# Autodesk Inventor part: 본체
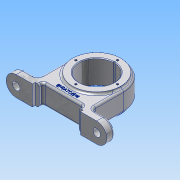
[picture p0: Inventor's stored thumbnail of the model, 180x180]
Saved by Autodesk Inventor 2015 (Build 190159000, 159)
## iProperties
Created: 2019-05
Part Number: 본체
Material: 알루미늄 6061
Document SubType Name: Modeling
Designer: user
Density: 2.7 g/cm^3
Appearance: 알루미늄 - 평지
Author: user
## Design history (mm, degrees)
sketch "스케치1"
  geometry: L1 (75, -15)-(-75, -15); L2 (-75, -15)-(-75, 15); L3 (-75, 15)-(75, 15); L4 (75, 15)-(75, -15); L5 (75, -15)-(-75, 15); L6 (-75, -15)-(75, 15); 1 further point
  constraints: 12 end point, 2 midpoint, 2 parallel, 1 horizontal, 1 perpendicular
  dimensions: "d0" = 150 distance of L2.end L3.end; "d1" = 30 distance of L1.end L2.end
extrude "돌출1" new body sketch "스케치1" distance "d2" = 12; taper "d3" = 0 deg
fillet "모깎기1" dims "d4" = 15
sketch "스케치2"
  geometry: L1 (60, 15)-(-60, 15) reference; L2 (36, -15)-(-36, -15); L3 (-36, -15)-(-36, 15); L4 (-36, 15)-(36, 15); L5 (36, 15)-(36, -15); L6 (36, -15)-(-36, 15); L7 (-36, -15)-(36, 15); 1 further point
  constraints: 12 end point, 2 midpoint, 2 parallel, 1 horizontal, 1 perpendicular, 1 point on line
  dimensions: "d5" = 72 distance of L3.end L4.end
extrude "돌출2" cut sketch "스케치2" distance "d6" = 4; taper "d7" = 0 deg
sketch "스케치3"
  geometry: L1 (-36, 15)-(36, 15) reference; L2 (30, -15)-(-30, -15); L3 (-30, -15)-(-30, 15); L4 (-30, 15)-(30, 15); L5 (30, 15)-(30, -15); L6 (30, -15)-(-30, 15); L7 (-30, -15)-(30, 15); 1 further point
  constraints: 12 end point, 2 midpoint, 2 parallel, 1 horizontal, 1 perpendicular, 1 point on line
  dimensions: "d8" = 60 distance of L3.end L4.end
extrude "돌출3" cut sketch "스케치3" distance "d9" = 6; taper "d10" = 0 deg
node "작업 평면1"
node "작업 평면2"
sketch "스케치10"
  geometry: C1 r 9 at (-60, 0); C2 r 9 at (60, 0); A1 r 15 centre (-60, 0) between (-60, 15) and (-60, -15) reference; A2 r 15 centre (60, 0) between (60, -15) and (60, 15) reference; 1 further point
  constraints: 2 centre point, 2 coincident
  dimensions: "d22" = 18 diameter of C1; "d23" = 18 diameter of C2
extrude "돌출8" join sketch "스케치10" distance "d24" = 3; taper "d25" = 0 deg
sketch "스케치11"
  geometry: C1 r 9 at (0, 0) reference; A1 r 15 centre (120, 0) between (120, -15) and (120, 15) reference; 3 further points
  constraints: 2 coincident
hole "구멍1" sketch "스케치11" at (0, 0), (120, 0) diameter "d26" = 11; stored, may be unused: countersink angle "d30" = 90 deg, drill point angle "d32" = 118 deg; dims "d27" = 6, "d28" = 4, "d29" = 2, "d31" = 8
fillet "모깎기4" dims "d66" = 3
fillet "모깎기5" dims "d67" = 3
node "작업 평면7"
sketch "스케치18"
  geometry: C1 r 40 at (60, 60); 1 further point
  constraints: 1 centre point
  dimensions: "d72" = 40 radius of C1; "d73" = 60 distance of point (60, 0) C1.centre
extrude "돌출10" join sketch "스케치18" stored distance "d74" = 30; taper "d75" = 0 deg
sketch "스케치19"
  geometry: C1 r 40 at (0, 0) reference; C2 r 36 at (0, 0); 1 further point
  constraints: 1 centre point, 1 coincident
  dimensions: "d76" = 72 diameter of C2
extrude "돌출11" join sketch "스케치19" distance "d77" = 3; taper "d78" = 0 deg
sketch "스케치20"
  geometry: C1 r 40 at (0, 0) reference; C2 r 36 at (0, 0); 1 further point
  constraints: 1 centre point, 1 coincident
  dimensions: "d79" = 72 diameter of C2
extrude "돌출12" join sketch "스케치20" distance "d80" = 3; taper "d81" = 0 deg
node "작업 평면8"
sketch "스케치21"
  geometry: L1 (20, 60)-(20, 11.494); L2 (100, 60)-(100, 11.494); L3 (20, 11.494)-(100, 11.494); A1 r 40 centre (60, 60) between (100, 60) and (20, 60) reference; 1 further point
  constraints: 6 end point, 2 point on circle, 2 tangent, 2 vertical, 1 perpendicular
extrude "돌출13" join sketch "스케치21" stored distance "d82" = 30; taper "d83" = 0 deg
hole "구멍5" diameter "d86" = 52; stored, may be unused: countersink angle "d90" = 90 deg, drill point angle "d92" = 0 deg; dims "d84" = 10, "d85" = 10, "d87" = 8, "d88" = 7, "d89" = 1, "d91" = 10
sketch "스케치22"
  geometry: 3 further points
  constraints: 1 vertical alignment, 1 other
hole "구멍6" sketch "스케치22" at (0, 26) diameter "d93" = 3; stored, may be unused: countersink angle "d97" = 90 deg, drill point angle "d99" = 0 deg; dims "d94" = 8, "d95" = 7, "d96" = 1, "d98" = 10
node "작업 평면9"
sketch "스케치23"
  geometry: 2 further points
  constraints: 1 coincident
hole "구멍7" sketch "스케치23" at (0, 0) diameter "d100" = 4.917; stored, may be unused: countersink angle "d104" = 90 deg, drill point angle "d106" = 118 deg; dims "d101" = 8, "d102" = 7, "d103" = 1, "d105" = 10
node "작업 평면11"
  node "작업 평면10"
sketch "스케치24"
  geometry: C1 r 1 at (0, 165.837); 1 further point
  constraints: 1 centre point, 1 coincident
  dimensions: "d108" = 2 diameter of C1
extrude "돌출14" cut sketch "스케치24" distance "d109" = 30; taper "d110" = 0 deg
sketch "스케치25" dims "d111" = 62
  geometry: C1 r 36 at (0, 0) reference; 3 further points
  constraints: 1 coincident, 1 vertical alignment, 2 other
hole "구멍8" sketch "스케치25" at (0, 31) diameter "d112" = 3.242; stored, may be unused: countersink angle "d116" = 90 deg, drill point angle "d118" = 118 deg; dims "d113" = 8, "d114" = 7, "d115" = 1, "d117" = 8
node "작업 평면12"
fillet "모깎기7" dims "d122" = 6
fillet "모깎기8" dims "d123" = 3
fillet "모깎기9" dims "d124" = 3
fillet "모깎기10" dims "d125" = 3
chamfer "모따기2" distance "d126" = 1; stored, may be unused: second distance "d127" = 2, angle "d128" = 45 deg
sketch "스케치26"
  geometry: L1 (33, 10)-(87, 10) reference; A1 r 39 centre (60, 60) between (23, 47.671) and (97, 47.671) reference; 2 further points
  constraints: 1 vertical alignment, 1 other
  dimensions: "d129" = 7 distance from line of point (60, 17) L1
extrude "돌출15" join sketch "스케치26" distance "d130" = 0.5; taper "d131" = 0 deg
node "솔리드1"
pattern_circular "원형 패턴2" dims angle "d120" = 360 deg
mirror "대칭2"
other parameters: "d107" = -2.75
